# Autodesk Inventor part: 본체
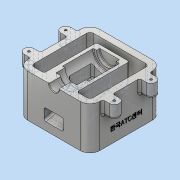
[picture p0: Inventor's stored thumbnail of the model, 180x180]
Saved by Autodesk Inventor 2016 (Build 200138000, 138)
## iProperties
Created: 2018-01
Part Number: 본체
Material: 알루미늄 6061
Document SubType Name: Modeling
Designer: Administrator
Density: 2.7 g/cm^3
Appearance: 알루미늄 - 평지
Mass: 999.24 g
Surface Area: 832.205 cm^2
Volume: 370.089 cm^3
Author: Administrator
## Parameters: d14 = 32 mm, d15 = 15 mm, d55 = 65 mm, d56 = 0, d57 = 105 deg, d61 = 0, d62 = 19 mm, d63 = 14 mm, d64 = 47 mm, d65 = 5 mm, d68 = 32 mm, d69 = 15 mm, d70 = 180 deg, d71 = 1 mm, d81 = 15 mm, d83 = 27 mm, d85 = 0, d88 = 3.242 mm, d89 = 9 mm, d90 = 4 mm, d91 = 2 mm, d92 = 90 deg, d93 = 11 mm, d94 = 118 deg, d97 = 56 mm, d101 = 18 mm, d102 = 0, d103 = 0, d104 = 5 mm, d106 = 35 mm, d107 = 37 mm, d110 = 0, d111 = 5 mm, d113 = 15 mm, d114 = 1 mm, d115 = 2 mm, d116 = 45 deg, d117 = 3 mm, d118 = 3 mm, d119 = 3 mm, d120 = 3 mm, d121 = 3 mm, d126 = 55 mm, d127 = 0.5 mm, d128 = 0, d130 = 3 mm, d131 = 3 mm, d132 = 3 mm
